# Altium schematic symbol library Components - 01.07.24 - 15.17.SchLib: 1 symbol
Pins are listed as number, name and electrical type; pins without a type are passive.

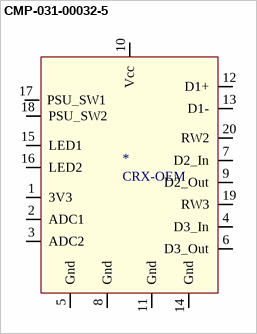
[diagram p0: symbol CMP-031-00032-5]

## CMP-031-00032-5
designator *, comment CRX-OEM
CRX OEM module
footprint CRX_OEM-SMD (CRX OEM Version SMD connection)
footprint CRX_OEM-THRU (Footprint not found)
footprint CRX_OEM-SMD (CRX OEM Version SMD connection)
footprint CRX_OEM-THRU (CRX OEM Version Thru hole connection)
pins: 1 3V3 (power), 2 ADC1, 3 ADC2, 4 D3_In, 5 Gnd, 6 D3_Out, 7 D2_In, 8 Gnd, 9 D2_Out, 10 Vcc, 11 Gnd, 12 D1+, 13 D1-, 14 Gnd, 15 LED1, 16 LED2, 17 PSU_SW1, 18 PSU_SW2, 19 RW3, 20 RW2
